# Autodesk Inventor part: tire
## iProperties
Author: vincent molino
Shininess: 20.0
Angle Display Precision: 2
Document Length Units: 11272
Document Angle Units: 11286
Document Time Units: 11279
Document Mass Units: 11290
Document Length Units Precision: 3
Document Angle Units Precision: 2
Compacted: True
PropertySet Name: _Private Model Information
Created: 2002-01
Part Number: tire
Document SubType Name: Modeling
Designer: vincent molino
Control State: 0
Master: False
Checked Out: False
PropertySet Name: Design Tracking Control
Density: 0.0
Volumn: 0.0
Area: 0.0
PropertySet Name: Model Information
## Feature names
1. Extrusion1
2. Extrusion2
3. Mirror1
4. Circular Pattern2
5. Extrusion3
6. Revolution1
7. Mirror2
